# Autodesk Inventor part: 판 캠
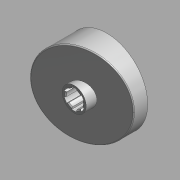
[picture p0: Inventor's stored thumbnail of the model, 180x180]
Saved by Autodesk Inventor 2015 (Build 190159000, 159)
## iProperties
Created: 2015-11
Part Number: 판 캠
Document SubType Name: 모델링
Designer: mdu
Material: 강철, 연강
Density: 7.86 g/cm^3
Appearance: 알루미늄 - 평지
Mass: 682.455 g
Surface Area: 331.303 cm^2
Volume: 86.8264 cm^3
변환 표준: STEP AP214IS
파일 이름: C:\Users\SeoGD\Desktop\?쒗뿕\??stp
전처리기: Build: 253, Release: 2010 SP1 - Date: Wed 07/29/2009
전송 단위: 밀리미터
불확실성: 0.01
Author: mdu
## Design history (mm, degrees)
node "작업 평면4"
sketch "스케치1"
  geometry: C1 r 44.5 at (0, 0); 1 further point
  constraints: 1 centre point, 1 coincident
  dimensions: "d25" = 89 diameter of C1
extrude "돌출1" new body sketch "스케치1" distance "d1" = 40; taper "d2" = 0 deg
sketch "스케치2"
  geometry: L1 (-44.5, 15)-(44.5, 38.847); L2 (-44.5, 0)-(-44.5, 40) reference; L3 (-44.5, 40)-(44.5, 40) reference; L4 (44.5, 0)-(44.5, 40) reference; 1 further point
  constraints: 2 end point, 2 point on line
  dimensions: "d26" = 15 distance of L2.start L1.start; "d27" = 75 deg angle of L1 L2
extrude "돌출2" cut sketch "스케치2" stored distance "d5" = 40; taper "d6" = 0 deg
node "작업 평면1"
sketch "스케치3"
  geometry: C1 r 13 at (0, 0); 1 further point
  constraints: 1 centre point, 1 coincident
  dimensions: "d9" = 26 diameter of C1
extrude "돌출3" join sketch "스케치3" distance "d10" = 38; taper "d11" = 0 deg
hole "구멍1" diameter "d14" = 18; stored, may be unused: countersink angle "d18" = 90 deg, drill point angle "d20" = 118 deg; dims "d12" = 10, "d13" = 10, "d15" = 6, "d16" = 4, "d17" = 2, "d19" = 8
feature "쉘2" dims "d29" = 5
sketch "스케치6"
  geometry: C1 r 17.5 at (0, 0); C2 r 14 at (0, 0) reference; 1 further point
  constraints: 1 centre point, 1 coincident
  dimensions: "d28" = 35 diameter of C1
extrude "돌출4" join sketch "스케치6" stored distance "d30" = 38; taper "d31" = 0 deg
fillet "모깎기1" dims "d32" = 3
chamfer "모따기1" distance "d21" = 1; stored, may be unused: second distance "d22" = 2, angle "d23" = 45 deg
sketch "스케치7"
  geometry: L1 (-12.374, 12.374)-(-27.931, 27.931); A1 r 39.5 centre (0, 0) between (-27.931, 27.931) and (0, 39.5) reference; 2 further points
  constraints: 2 end point, 2 point on circle, 1 point on line, 1 vertical alignment, 2 other
  dimensions: "d33" = 45 deg dimension on point (0, 0) L1.start A1.end
feature "리브1" sketch "스케치7" dims "d34" = 5, "d35" = 1, "d36" = 0
fillet "모깎기2" dims "d37" = 3
sketch "스케치8"
  geometry: L1 (2.5, 10.712)-(2.5, 8.646); L2 (-2.5, 10.712)-(-2.5, 8.646); A1 r 11 centre (0, 0) between (2.5, 10.712) and (-2.5, 10.712); A2 r 9 centre (0, 0) between (2.5, 8.646) and (-2.5, 8.646) reference; 1 further point
  constraints: 4 end point, 4 point on circle, 2 parallel, 1 centre point, 1 coincident, 1 vertical
  dimensions: "d41" = 22 diameter of A1; "d42" = 5 distance between parallel lines of L1 L2
extrude "돌출5" cut sketch "스케치8" stored distance "d43" = 38; taper "d44" = 0 deg
fillet "모깎기3" dims "d48" = 1
node "솔리드1"
node "솔리드 본체"
node "곡면 본체"
pattern_circular "원형 패턴1" dims angle "d39" = 360 deg
pattern_circular "원형 패턴2" dims angle "d46" = 360 deg
node "솔리드2"
